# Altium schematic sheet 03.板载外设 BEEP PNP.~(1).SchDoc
size A4; CheckedBy: <审核日期>; Author: 黄雄波; CompanyName: 广州周立功单片机科技有限公司; DocumentNumber: 3; SheetNumber: 3; SheetTotal: 7; PageSetup: Record=PageOptions¦CenterHorizontal=True¦CenterVertical=True¦PrintScale=1.00¦XCorrection=1.00¦YCorrection=1.00¦PrintKind=0¦BorderSize=5000000¦LeftOffset=0¦BottomOffset=0¦Orientation=2¦PaperLength=1000¦PaperWidth=1000¦Scale=100¦PaperSource=7¦PrintQuality=600¦MediaType=1¦DitherType=10¦PaperKind=A4¦PrintScaleMode=1; DesignDate: 2016-12-29; CheckDate: <审核人员>; SheetName: 板载外设; SheetVersion: V1.01; SheetDescription: 板载外设; productModel: AM116-Core; productName: 开发套件
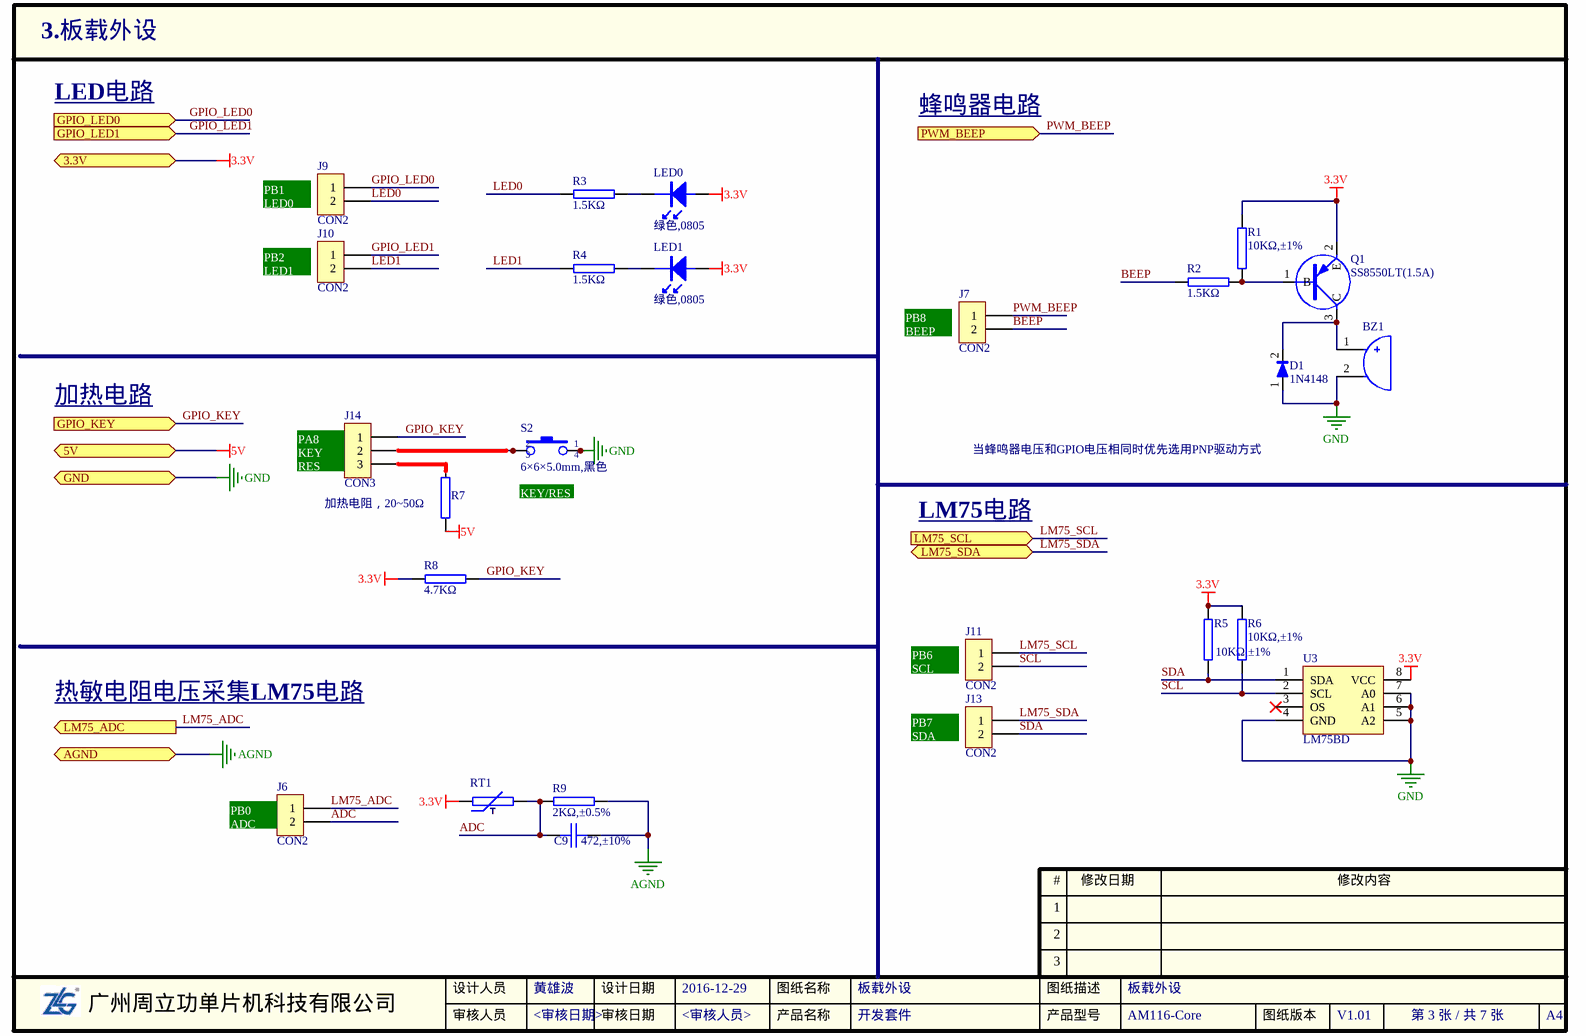
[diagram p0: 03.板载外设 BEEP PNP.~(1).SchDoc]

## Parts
BZ1  BUZZER2  [BUZZ-4/9]  (value not drawn)
C9  472,±10%  [0603C]
D1  value 1N4148  [SOD-323]  (hidden comment: DIODE1)
J6  CON2  [SIP-2-2.54]
J7  CON2  [SIP-2-2.54]
J9  CON2  [SIP-2-2.54]
J10  CON2  [SIP-2-2.54]
J11  CON2  [SIP-2-2.54]
J13  CON2  [SIP-2-2.54]
J14  CON3  [SIP-3-2.54]
LED0  value 绿色,0805  [LED-0805]  (hidden comment: LED1)
LED1  value 绿色,0805  [LED-0805]  (hidden comment: LED1)
Q1  value SS8550LT(1.5A)  [SOT-23]  (hidden comment: PNP-1)
R1  10KΩ,±1%  [0603R]
R2  1.5KΩ  [0603R]
R3  1.5KΩ  [0603R]
R4  1.5KΩ  [0603R]
R5  10KΩ,±1%  [0603R]
R6  10KΩ,±1%  [0603R]
R7  20Ω,±5%  [RESAD1778W80L1450D430P]  (value not drawn)
R8  4.7KΩ  [0603R]
R9  2KΩ,±0.5%  [0603R]
RT1  MF52E-103F3435FB-A(2.5MM)  [RES-NTC(2.0)]  (value not drawn)
S2  value 6×6×5.0mm,黑色  [KEY-6S]  (hidden comment: SW-PB4P)
U3  value LM75BD  [SOIC127P600X175-8N]  (hidden comment: LM75B)

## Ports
3.3V, 5V, AGND, GND, GPIO_KEY (in), GPIO_LED0 (in), GPIO_LED1 (in), LM75_ADC (out), LM75_SCL (in), LM75_SDA (bidir), PWM_BEEP (in)

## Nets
3.3V: LED0.1 LED1.1 Q1.2(E) R1.2 R5.2 R6.2 R8.2 RT1.1 U3.8(VCC) ; port 3.3V
5V: R7.1 ; port 5V
AGND: C9.2 R9.2 ; port AGND
GND: BZ1.2(B) D1.1 S2.1 S2.4 U3.4(GND) U3.5(A2) U3.6(A1) U3.7(A0) ; port GND
ADC: C9.1 J6.2 R9.1 RT1.2
BEEP: J7.2 R2.1
GPIO_KEY: J14.1 R8.1 ; port GPIO_KEY
GPIO_LED0: J9.1 ; port GPIO_LED0
GPIO_LED1: J10.1 ; port GPIO_LED1
LED0: J9.2 R3.2
LED1: J10.2 R4.2
LM75_ADC: J6.1 ; port LM75_ADC
LM75_SCL: J11.1 ; port LM75_SCL
LM75_SDA: J13.1 ; port LM75_SDA
PWM_BEEP: J7.1 ; port PWM_BEEP
SCL: J11.2 R6.1 U3.2(SCL)
SDA: J13.2 R5.1 U3.1(SDA)
NetBZ1_1: BZ1.1(A) D1.2 Q1.3(C)
NetJ14_2: J14.2 S2.2 S2.3
NetJ14_3: J14.3 R7.2
NetLED0_2: LED0.2 R3.1
NetLED1_2: LED1.2 R4.1
NetQ1_1: Q1.1(B) R1.1 R2.2

Not connected (* = marked no-connect by the designer): U3 3(OS)*

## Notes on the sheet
- LED电路
- 蜂鸣器电路
- (near J9) PB1
  LED0
- (near J10) PB2
  LED1
- (near J7) PB8
  BEEP
- 加热电路
- (near J14) PA8
  KEY
  RES
- 加热电阻，20~50Ω
- (near S2) KEY/RES
- LM75电路
- 当蜂鸣器电压和GPIO电压相同时优先选用PNP驱动方式
- 热敏电阻电压采集LM75电路
- (near J11) PB6
  SCL
- (near J13) PB7
  SDA
- (near J6) PB0
  ADC

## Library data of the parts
BZ1 = 1.06.09.0016: Buzzer有极性; Value: AS-905I-LF,无源; 名称: 讯响器; 厂商: 常州笠翔; 型号: AS-905I-LF,无源,Ф9×4.8mm; 贴片和直插: THT; PCB备注: Flq-Shcj-Twrj-150113; 器件优选方案: 量产物料,优先选用
C9 = 1.02.01.0057: Capacitor; 名称: 电容; 封装: 0603; 设备封装名称: C0603_820PF_COG_50V_5%; 厂商: muRata; 型号: 472,±10%,50V,X7R; 贴片和直插: SMT; 器件优选方案: 状态正常
D1 = 1.04.07.0027: 1N4148,SOD-323,RoHS; 名称: 二极管; 设备封装名称: SOD-323_1N4148; 贴片和直插: SMT
J6 J7 J9-J11 J13 = CON2: Connector
J14 = CON3: Connector
LED0 LED1 = 1.04.05.0002: 绿色,0805,0805,RoHS; 名称: 发光二极管; 封装: 0805; 设备封装名称: LED0805-GREEN; 贴片和直插: SMT; 器件优选方案: 样品物料,谨慎选用
Q1 = 1.04.09.0002: PNP Transistor; 名称: 三极管; 设备封装名称: SOT-23_SS8550LT; 厂商: 江苏长电; 贴片和直插: SMT
R1 = 1.01.01.0052: 10KΩ,±1%,0603,*,RoHS; 名称: 电阻; 封装: 0603; 设备封装名称: R0603_10K_1%; 厂商: Ralec; 贴片和直插: SMT
R2 = 1.01.01.0037: 1.5KΩ,0603,*,RoHS; 名称: 电阻; 封装: 0603; 设备封装名称: R0603_1.5K; 厂商: Ralec; 贴片和直插: SMT; 器件优选方案: 状态正常
R3 R4 = 1.01.01.0037: 1.5KΩ,0603,*,RoHS; 名称: 电阻; 封装: 0603; 设备封装名称: R0603_1.5K; 厂商: Ralec; 贴片和直插: SMT; 器件优选方案: 正常状态，可以选用
R5 R6 = 1.01.01.0052: 10KΩ,±1%,0603,*,RoHS; 名称: 电阻; 封装: 0603; 设备封装名称: R0603_10K_1%; 厂商: Ralec; 贴片和直插: SMT; 器件优选方案: 正常状态，可以选用
R7 = 1.01.10.0003: 20Ω,±5%,2W,Ф5.5×16mm,RoHS; 名称: 电阻; 贴片和直插: THT
R8 = 1.01.01.0045: 4.7KΩ,0603,*,RoHS; 名称: 电阻; 封装: 0603; 设备封装名称: R0603_4.7K; 厂商: Ralec; 贴片和直插: SMT; 器件优选方案: 正常状态，可以选用
R9 = 1.01.01.0084: 名称: 电阻; 封装: 0603; 设备封装名称: R0603_2K_0.5%; 厂商: Ralec; 贴片和直插: SMT
RT1 = 1.01.14.0011: MF52E-103F3435FB-A(2.5MM),THT,RoHS; 名称: 热敏电阻; 器件优选方案: 正常状态，可以选用
S2 = 1.09.01.0003: 6×6×5.0mm,黑色,SMD,,*; 名称: 轻触按键; 贴片和直插: SMT
U3 = 1.05.10.0602: LM75BD,SO-9,NXP,RoHS; 名称: IC; 封装: SO-8; 贴片和直插: SMT; 器件优选方案: 样品物料,谨慎选用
